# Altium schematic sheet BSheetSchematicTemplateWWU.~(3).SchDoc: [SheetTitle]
size B; Date: [Date]
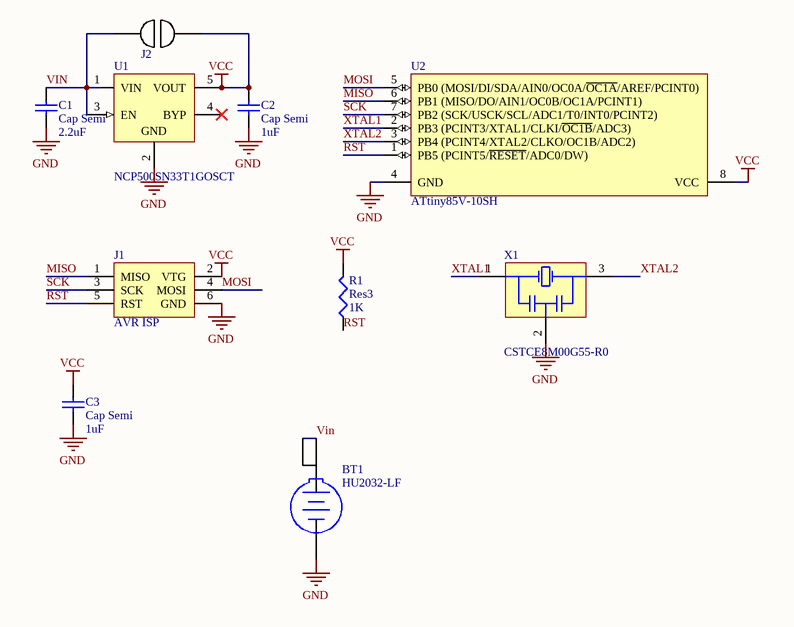
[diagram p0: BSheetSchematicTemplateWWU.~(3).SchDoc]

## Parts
BT1  HU2032-LF  [RENA-HU2032-LF_V]
C1  Cap Semi  value 2.2uF  [1608[0603]]
C2  Cap Semi  value 1uF  [1608[0603]]
C3  Cap Semi  value 1uF  [1608[0603]]
J1  AVR ISP  [AVR_ISP]
J2  SOLDER JUMPER  [SOLDER JUMPER]  (value not drawn)
R1  Res3  value 1K  [J1-0603]
U1  NCP500SN33T1GOSCT  [ONSC-SOT23-5_L]
U2  ATtiny85V-10SH  [8S2_N]
X1  CSTCE8M00G55-R0  [MURA-CSTCE_G_A-3_V]

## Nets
GND: BT1.3(-) C1.1 C2.1 C3.1 J1.6(GND) U1.2(GND) U2.4(GND) X1.2(GND)
VCC: C2.2 C3.2 J1.2(VTG) J2.2 R1.2 U1.5(VOUT) U2.8(VCC)
MISO: J1.1(MISO) U2.6(PB1_(MISO/DO/AIN1/OC0B/OC1A/PCINT1))
MOSI: J1.4(MOSI) U2.5(PB0_(MOSI/DI/SDA/AIN0/OC0A/~{OC1A}/AREF/PCINT0))
RST: J1.5(RST) R1.1 U2.1(PB5_(PCINT5/~{RESET}/ADC0/DW))
SCK: J1.3(SCK) U2.7(PB2_(SCK/USCK/SCL/ADC1/T0/INT0/PCINT2))
VIN: BT1.1(+) BT1.2(+) C1.2 J2.1 U1.1(VIN) U1.3(EN)
XTAL1: U2.2(PB3_(PCINT3/XTAL1/CLKI/~{OC1B}/ADC3)) X1.1(X1)
XTAL2: U2.3(PB4_(PCINT4/XTAL2/CLKO/OC1B/ADC2)) X1.3(X2)

Not connected (* = marked no-connect by the designer): U1 4(BYP)*

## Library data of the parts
BT1 = CMP-2000-06429-1: Coin Cell Battery Holder, CR2032, Horizontal, -40 to 100 degC, 3-Pin THD, RoHS, Tray; Brand: Renata; Battery Cell Size: 20mm
C1-C3 = Cap Semi: Capacitor (Semiconductor SIM Model)
J1 = AVR_ISP: AVR ISP POGO CONNECTOR
J2 = SOLDER JUMPER: Solder Jumper (1mm)
R1 = Res3: Resistor
U1 = CMP-0273-00001-2: Fixed Low Drop Positive Voltage Regulator, 3.3V, 5-Pin TSOT-23, Tape and Reel; Manufacturer: ON Semiconductor; PartNumber: CAT6219-330TDGT3; PSRR (dB): 64; VI Max (V): 5.5; Output: Single; Iq Typ (mA): 0.085; Noise (uVrms): 45; VDO Typ (V): 0.3; Io Typ(A): 0.5; Vo(V): 3.3
U2 = CMP-0093-00338-1: 8-bit AVR Microcontroller, 10MHz, 1.8-5.5V, 8K Flash, 512 Bytes EEPROM, 512 Bytes SRAM, Industrial Grade (-40°C to 85°C), 8-Lead SOIC, Pb-Free
X1 = CMP-2100-03620-1: Ceramic Resonator, 8 MHz, +/- 0.5%, -20 to 80 degC, 3-Pin SMD, RoHS, Tape and Reel; Manufacturer: Murata; Capacitance: 33pF; Frequency Stability: 0.2%; Self Resonant Frequency: 8MHz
